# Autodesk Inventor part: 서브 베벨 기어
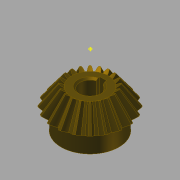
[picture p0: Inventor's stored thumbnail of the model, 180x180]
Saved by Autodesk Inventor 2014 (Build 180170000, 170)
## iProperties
Created: 2014-10
Part Number: 서브 베벨 기어
Material: 강철, 탄소
Document SubType Name: Modeling
Designer: KYOUNG IL JANG
Categories: <?xml version="1.0" encoding="UTF-16"?> <MemberInstance><Categories><FamilyTemplate><FamilyTemplateParameter ValueType="xs:double" Id="1" ObjectReferenceKey="da
Mass: 135.037 g
Surface Area: 63.6518 cm^2
Volume: 17.1585 cm^3
Density: 7.87 g/cm^3
Appearance: Brindle
CustomPartVersion: 1
Author: SeoGD™ [www.esajin.kr]
Revision Number: 1
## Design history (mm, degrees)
node "맨 위 점"
node "메쉬 평면2"
sketch "톱니 본체 스케치"
  geometry: L1 (0, 0)-(18.003, -31.331); L2 (18.003, -31.331)-(21.664, -28.891); L3 (21.664, -28.891)-(0, 0); L4 (20, -30)-(0, 0); L5 (10.813, -18.818)-(13.012, -17.352); L6 (18.003, -31.331)-(10.813, -18.818); L7 (21.664, -28.891)-(13.012, -17.352); L8 (0, -39.387)-(0, 6.564) reference; L9 (0, -30)-(21.664, -30)
  constraints: 16 end point, 4 point on line, 3 perpendicular, 2 collinear, 1 horizontal alignment, 1 vertical alignment
  dimensions: "d0" = 40 diameter of L4.start L8 (= da_de); "d1" = 36.00616 diameter of L1.end L8 (= da_dfe); "d2" = 43.3282 diameter of L2.end L8 (= da_dae); "d3" = 14.4 distance between parallel lines of L2 L5 (= da_b); "d4" = 28.8906 vertical distance of L2.end L1.start (= da_ve)
revolve "톱니 본체" sketch "톱니 본체 스케치" stored, may be unused: angle "d5" = 90 deg
node "시작점"
node "톱니 평면"
sketch "시작 스케치"
  geometry: L1 (0, -23.505)-(0, 10.645) reference; L2 (-0.834, -2.928)-(0.834, -2.928); A1 r 8.898 centre (-9.698, -3.713) between (-0.834, -2.928) and (-3.903, 3.04); A2 r 8.898 centre (9.698, -3.713) between (3.903, 3.04) and (0.834, -2.928); A3 r 27.357 centre (0, -24.037) between (3.903, 3.04) and (-3.903, 3.04); 1 further point
  constraints: 6 point on circle, 3 centre point, 3 symmetric about line, 2 end point, 1 coincident, 1 perpendicular, 1 other
  dimensions: "d7" = 8.89846 radius of A1 (= fd_rr); "d8" = 9.69794 horizontal distance of point (0, -24.037) A1.centre (= fd_x); "d9" = 20.32439 vertical distance of point (0, -24.037) A1.centre (= fd_y); "d57" = 27.35701 radius of A3 (= 0.5 x fd_dva + 0.3 x da_he); "d58" = 21.10901 distance from line of A3.centre L2 (= 0.5 x fd_dva - 1.12 x da_he)
node "끝점"
  node "끝 평면"
sketch "3D 스케치 오른쪽"
  node "Helical Curve Right" dims "d65" = 229.90621 (computed from da_dm, da_delta, da_beta), "d66" = 31.5, "d67" = 40 (= da_de), "d68" = -5.88003 (= -da_delta), "d69" = 12.16458 (computed from fd_loft, da_delta)
node "끝 평면 오른쪽"
sketch "끝 스케치 오른쪽"
  geometry: L1 (0, -22.649)-(0, 12.15) reference; L2 (-0.497, -1.72)-(0.497, -1.72); A1 r 5.299 centre (-5.775, -2.187) between (-0.497, -1.72) and (-2.324, 1.834); A2 r 5.299 centre (5.775, -2.187) between (2.324, 1.834) and (0.497, -1.72); A3 r 16.291 centre (0, -14.29) between (2.324, 1.834) and (-2.324, 1.834); 1 further point
  constraints: 6 point on circle, 3 centre point, 3 symmetric about line, 2 end point, 1 coincident, 1 perpendicular, 1 other
  dimensions: "d70" = 5.77526 horizontal distance of A3.centre A1.centre (computed from fd_x, fd_ratio); "d71" = 12.10346 vertical distance of point (0, -14.29) A1.centre (computed from fd_y, fd_ratio); "d72" = 5.29916 radius of A1 (computed from fd_rr, fd_ratio); "d73" = 12.57071 distance from line of point (0, -14.29) L2 (computed from d58, fd_ratio); "d74" = 16.29149 radius of A3 (computed from d57, fd_ratio)
feature "로프트 오른쪽" sketch "끝 스케치 오른쪽" dims "d75" = 0, "d77" = 0, "d79" = 0, "d80" = 90 deg, "d85" = 20, "d92" = 90 deg, "d93" = 90 deg, "da_teethtype" = 0 [user parameter]
sketch "3D 스케치 왼쪽"
  node "Helical Curve Left" dims "d26" = 229.90621 (computed from da_dm, da_delta, da_beta), "d27" = 12.16458 (computed from fd_loft, da_delta), "d28" = 40 (= da_de), "d29" = -5.88003 (= -da_delta)
node "끝 평면 왼쪽"
sketch "끝 스케치 왼쪽" dims "d56" = 10.82768 (derived)
  geometry: L1 (0, -35.087)-(0, 18.089) reference; L2 (-0.497, -1.716)-(0.497, -1.716); A1 r 5.299 centre (-5.775, -2.183) between (-0.497, -1.716) and (-2.324, 1.838); A2 r 5.299 centre (5.775, -2.183) between (2.324, 1.838) and (0.497, -1.716); A3 r 16.291 centre (0, -14.287) between (2.324, 1.838) and (-2.324, 1.838); 2 further points; 1 other entity
  constraints: 6 point on circle, 3 centre point, 3 symmetric about line, 2 end point, 1 coincident, 2 other
  dimensions: "d30" = 5.29916 radius of A1 (computed from fd_rr, fd_ratio); "d31" = 5.77526 horizontal distance of point (0, -14.287) A1.centre (computed from fd_x, fd_ratio); "d32" = 12.10346 vertical distance of A1.centre point (0, -14.287) (computed from fd_y, fd_ratio); "d61" = 16.29149 radius of A3 (computed from d57, fd_ratio); "d62" = 12.57071 distance from line of point (0, -14.287) L2 (computed from d58, fd_ratio)
feature "로프트 왼쪽" sketch "끝 스케치 왼쪽" dims "d35" = 0, "d37" = 0, "d39" = 0, "d40" = 90 deg, "d84" = 10, "d90" = 90 deg, "d91" = 90 deg, "da_teethtype" = 0 [user parameter]
sketch "본체 스케치"
  geometry: L1 (0, -35.038)-(0, -19.531) reference; L2 (18.003, -31.331)-(10.813, -18.818) reference; L3 (10.813, -18.818)-(0, -18.818); L4 (18.003, -31.331)-(0, -31.331)
  constraints: 4 end point, 2 perpendicular, 2 point on line
revolve "본체 고정" sketch "본체 스케치" stored, may be unused: angle "d46" = 90 deg
feature "피치 지름" dims angle "d47" = 90 deg
sketch "스케치8"
  geometry: C1 r 17 at (0, 0); 1 further point
  constraints: 1 centre point, 1 coincident
  dimensions: "d94" = 34 diameter of C1
extrude "돌출1" join sketch "스케치8" distance "d95" = 10; taper "d96" = 0 deg
sketch "스케치9"
  geometry: 1 further point
hole "구멍1" sketch "스케치9" at (0, 0) diameter "d97" = 12; stored, may be unused: countersink angle "d101" = 90 deg, drill point angle "d103" = 118 deg; dims "d98" = 6, "d99" = 4, "d100" = 2, "d102" = 8
sketch "스케치10"
  geometry: 1 further point
sketch "스케치11"
  geometry: 1 further point
sketch "스케치12"
  geometry: L1 (-2, 5.657)-(-2, 7.8); L2 (-2, 7.8)-(2, 7.8); L3 (2, 7.8)-(2, 5.657); A1 r 6 centre (0, 0) between (-2, 5.657) and (2, 5.657) reference; 1 further point
  constraints: 6 end point, 2 parallel, 2 point on circle, 1 perpendicular, 1 vertical
  dimensions: "d104" = 4 distance of L1.end L2.end; "d105" = 13.8 dimension on A1 L2
extrude "돌출2" cut sketch "스케치12" stored distance "d106" = 7; taper "d107" = 0 deg
chamfer "모따기1" distance "d108" = 1; stored, may be unused: second distance "d109" = 2, angle "d110" = 45 deg
body "Solid1"
feature "로프트" dims "d17" = 0, "d18" = 90 deg, "d19" = 0, "d20" = 90 deg, "d89" = 0, "da_teethtype" = 0 [user parameter]
pattern_circular "원형 패턴" dims angle "d22" = 360 deg, "d88" = 0, "da_teethtype" = 0 [user parameter]
pattern_circular "원형 패턴 오른쪽" dims angle "d82" = 360 deg, "da_teethtype" = 0 [user parameter]
pattern_circular "원형 패턴 왼쪽" dims angle "d42" = 360 deg, "da_teethtype" = 0 [user parameter]
sketch "끝 스케치"
  geometry: L1 (0, -15.359)-(0, 6.983) reference; L2 (-0.497, -1.72)-(0.497, -1.72); A1 r 5.299 centre (-5.775, -2.187) between (-0.497, -1.72) and (-2.324, 1.834); A2 r 5.299 centre (5.775, -2.187) between (2.324, 1.834) and (0.497, -1.72); A3 r 16.291 centre (0, -14.29) between (2.324, 1.834) and (-2.324, 1.834); 1 further point
  constraints: 6 point on circle, 3 centre point, 3 symmetric about line, 2 end point, 1 coincident, 1 other
  dimensions: "d12" = 5.29916 radius of A1 (computed from fd_rr, fd_ratio); "d15" = 5.77526 horizontal distance of A1.centre point (0, -14.29) (computed from fd_x, fd_ratio); "d16" = 12.10346 vertical distance of A1.centre point (0, -14.29) (computed from fd_y, fd_ratio); "d59" = 16.29149 radius of A3 (computed from d57, fd_ratio); "d60" = 12.57071 distance from line of A3.centre L2 (computed from d58, fd_ratio)
sketch "Sketch6"
  geometry: L1 (20, -30)-(0, 0) reference; L2 (0, -37.8)-(0, 6.3) reference
body "Srf1"
other parameters: "da_b" = 14.4 [user parameter; used in 2 equation terms], "da_de" = 40 [user parameter; used in 4 equation terms], "da_dae" = 43.3282 [user parameter; used in 2 equation terms], "da_dfe" = 36.00616 [user parameter; used in 1 equation term], "da_le" = 36.05551 [user parameter; used in 1 equation term], "da_omega" = 90 deg [user parameter; used in 1 equation term], "da_beta" = 0 [user parameter; used in 2 equation terms], "da_delta" = 5.88003 [user parameter; used in 8 equation terms], "da_alpha" = 20 deg [user parameter; used in 2 equation terms], "da_he" = 4.4 [user parameter; used in 4 equation terms], "da_ve" = 28.8906 [user parameter; used in 1 equation term], "fd_dv" = 48.07402 (computed from da_de, da_delta) [user parameter; used in 1 equation term], "fd_dva" = 52.07402 (computed from da_dae, da_delta) [user parameter; used in 3 equation terms], "fd_dvb" = 45.1748 (computed from fd_dv, da_alpha) [user parameter; used in 2 equation terms], "da_zv" = 240.37008 [user parameter; used in 1 equation term], "fd_loft" = 14.62 (= da_b + 0.05 x da_he) [user parameter; used in 4 equation terms], "fd_ratio" = 5.95514 (computed from da_le, fd_loft) [user parameter; used in 15 equation terms], "fd_rr" = 8.89846 (computed from fd_dd, fd_dvb) [user parameter; used in 6 equation terms], "fd_angle" = 0.66075 (computed from da_zv) [user parameter; used in 4 equation terms], "fd_x1" = 1.58709 (computed from da_dvw, fd_angle) [user parameter; used in 1 equation term], "fd_y1" = 23.98456 (computed from da_dvw, fd_angle) [user parameter; used in 1 equation term], "fd_x2" = 8.11084 (computed from fd_rr, fd_angle2, fd_angle) [user parameter; used in 1 equation term], "fd_y2" = 3.66016 (computed from fd_rr, fd_angle2, fd_angle) [user parameter; used in 1 equation term], "fd_x" = 9.69794 (= fd_x1 + fd_x2) [user parameter; used in 4 equation terms], "fd_y" = 20.32439 (= fd_y1 - fd_y2) [user parameter; used in 4 equation terms], "fd_angle2" = 3.57832 (computed from fd_dvb, fd_dd, da_alpha) [user parameter; used in 2 equation terms], "fd_dd" = 48.55402 (= fd_dva - 0.8 x da_he) [user parameter; used in 2 equation terms], "da_dvw" = 48.07402 [user parameter; used in 2 equation terms], "d11" = 14.62 (= fd_loft), "da_dm" = 32.01232 [user parameter; used in 2 equation terms], "da_x" = 0 [user parameter], "da_m" = 2 [user parameter], "d48" = 0, "d49" = 0, "d50" = 90 deg (= da_omega), "d51" = 9 deg (computed from da_z), "d52" = 0, "d53" = 0, "d54" = 0
